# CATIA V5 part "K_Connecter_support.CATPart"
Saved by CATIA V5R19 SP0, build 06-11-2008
Part number: Connecter_support
Bounding box of the stored display mesh (mm): x -21.875 to 71.875, y -243.303 to -216.303, z 28.564 to 62.064
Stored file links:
  G:\Khaled_CFAO_2011\SIL\SIL_GR2\ctanaphiko\Khaled\CAD_ThinkMOTION\K_Connecter_support.CATPart
  G:\Khaled_CFAO_2011\SIL\SIL_GR2\ctanaphiko\CATIA\Conception_Tripod.CATProduct
  D:\DATA\H310824\My Documents\CFAO\Leg.CATPart
  G:\Khaled_CFAO_2011\SIL\SIL_GR2\ctanaphiko\CATIA\Squelette.CATPart
  G:\Khaled_CFAO_2011\SIL\SIL_GR2\ctanaphiko\Khaled\CAD_ThinkMOTION\K_Leg_Level1.CATPart
  G:\Khaled_CFAO_2011\SIL\SIL_GR2\ctanaphiko\Khaled\CAD_ThinkMOTION\K_Part8.CATPart
  G:\Khaled_CFAO_2011\SIL\SIL_GR2\ctanaphiko\CATIA\Support_camera.CATPart
  G:\Khaled_CFAO_2011\SIL\SIL_GR2\ctanaphiko\Khaled\CAD_ThinkMOTION\K_Ground_contact.CATPart
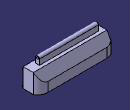
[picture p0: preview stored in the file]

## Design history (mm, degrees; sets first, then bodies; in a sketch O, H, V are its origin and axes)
External parameters (linked from other documents)
  External.Depth_pocket = 15 mm
  External.Dia_Leg_Step1 = 18 mm
  External.Width_Leg_Support = 75 mm
AxisSystem1: origin (0, 0, 0), X (1, 0, 0), Y (0, 1, 0), Z (0, 0, 1)
Set1
  Plane1 "Plan_Ref": linked copy from another document
  Point1: linked copy from another document
  Point2: linked copy from another document
  DatumPoint1: linked copy from another document
  DatumPoint2: linked copy from another document
  DatumCurve1: linked copy from another document
  DatumCurve2: linked copy from another document
  Plane2: linked copy from another document
  Plane3: linked copy from another document
  Point3: linked copy from another document
  Plane4: linked copy from another document
Body1 (main body)
  Sketch1 on Plane5, origin (22.5, 0, 0), H (0, 1, 0), V (0, 0, 1)
    line L1 (-232.3033, 48.8501) -> (-232.3033, 59.5643)
    arc A1 centre (-229.8033, 59.5643) radius 2.5 from (-232.3033, 59.5643) to (-227.3033, 59.5643) cw
    line L2 (-227.3033, 59.5643) -> (-227.3033, 48.8501)
    line L3 (-227.3033, 48.8501) -> (-232.3033, 48.8501)
    circle A2 centre (-229.8033, 59.5643) radius 1.5
    reference projected point E1 (-229.8033, 54.2072) from Point2
    reference projected point E2 (-229.8033, 54.2072) from Point2
    radius A1 = 2.5 {= External.Width_Leg_Support /30}
    radius A2 = 1.5 {= Sketch1.radius(A1) -1mm}
    length L2 = 10.7143 {= External.Width_Leg_Support /7}
    distance E1 L3 = 5.3571 {= Sketch1.length(L2) /2}
    distance E2 L2 = 2.5 {= Sketch1.radius(A1)}
    vertical: L1 V, L2 V
    tangency: A1 L1, L2 A1
    horizontal: L3 H
  Pad1: profile Sketch1, direction (1, 0, 0), length 37.5 {= (External.Width_Leg_Support)*0.5}, mirrored extent
  Body2
    Sketch2 on ZX plane of AxisSystem1, origin (0, 0, 0), H (0, 0, 1), V (1, 0, 0)
      point P1 (61.3501, 95)
      point P2 (52.7072, -21.875)
      line L1 (52.7072, -21.875) -> (52.7072, 71.875)
      line L2 (52.7072, 71.875) -> (36.5643, 71.875)
      point P4 (36.5643, 71.875)
      line L3 (36.5643, 71.875) -> (36.5643, -21.875)
      line L4 (36.5643, -21.875) -> (52.7072, -21.875)
      point P6 (52.7072, -21.875)
      reference projected point E1 (54.2072, -10.5316) from Point1
      reference projected point E2 (54.2072, -10.5316) from Point1
      point P8 (59.5643, 60)
      length L3 = 93.75 {= External.Width_Leg_Support *5/4}
      distance P8 P4 V = 11.875 {= (Sketch2.length(L3) -(External.Width_Leg_Support-5mm) )/2}
      distance L1 E1 = 1.5
      distance E2 L3 = 17.6429
      vertical: L1 V, L3 V
      coincidence: P6 P2
      horizontal: L4 H, L2 H
    Sketch3 on XY plane of AxisSystem1, origin (0, 0, 0), H (1, 0, 0), V (0, 1, 0)
      construction line L1 (-15, -229.8033) -> (60, -229.8033)
      point P1 (-15, -229.8033)
      point P2 (60, -229.8033)
      line L2 (-15, -216.3033) -> (60, -216.3033)
      line L3 (60, -243.3033) -> (-15, -243.3033)
      arc A1 centre (60, -229.8033) radius 13.5 from (60, -216.3033) to (60, -243.3033) cw
      arc A2 centre (-15, -229.8033) radius 13.5 from (-15, -243.3033) to (-15, -216.3033) cw
      reference projected line E1 (60, -232.3033) -> (60, -227.3033) from edge [face of Pad1 from Sketch1.L3 | end face of Pad1]
      reference projected line E2 (-15, -232.3033) -> (-15, -227.3033) from edge [start face of Pad1 | face of Pad1 from Sketch1.L3]
      distance L1 L2 = 13.5 {= External.Dia_Leg_Step1*3/4}
      horizontal: L1 H
      tangency: A1 L2, A2 L2, A1 L3, A2 L3
      midpoint: P2 E1, P1 E2
    SolidCombine1: FirstComponentProfile Sketch2, FirstComponentDirection Sketch2, SecondComponentProfile Sketch3, SecondComponentDirection Sketch3
    Chamfer1: length 7, angle 60, on edge [face of SolidCombine1 from Sketch2.L1 | face of SolidCombine1 from Sketch3.L2]; edge [face of SolidCombine1 from Sketch2.L1 | face of SolidCombine1 from Sketch3.L3]
    Thickness1: Thickness 8, Face face of SolidCombine1 from Sketch2.L3
  Add1: tool Body2
  Sketch4 on face of SolidCombine1 from Sketch2.L3, origin (0, 0, 28.5643), H (1, 0, 0), V (0, -1, 0)
    projected circle E1 centre (-10.5316, 229.8033) radius 9 from edge of DatumCurve1
    projected circle E2 centre (55.5316, 229.8033) radius 9 from edge of DatumCurve2
  Pocket1: profile Sketch4, direction (0, 0, 1), length 5
Body3
  Plane5: type OffsetPt, RefPlane Plane4, RefPoint Point3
